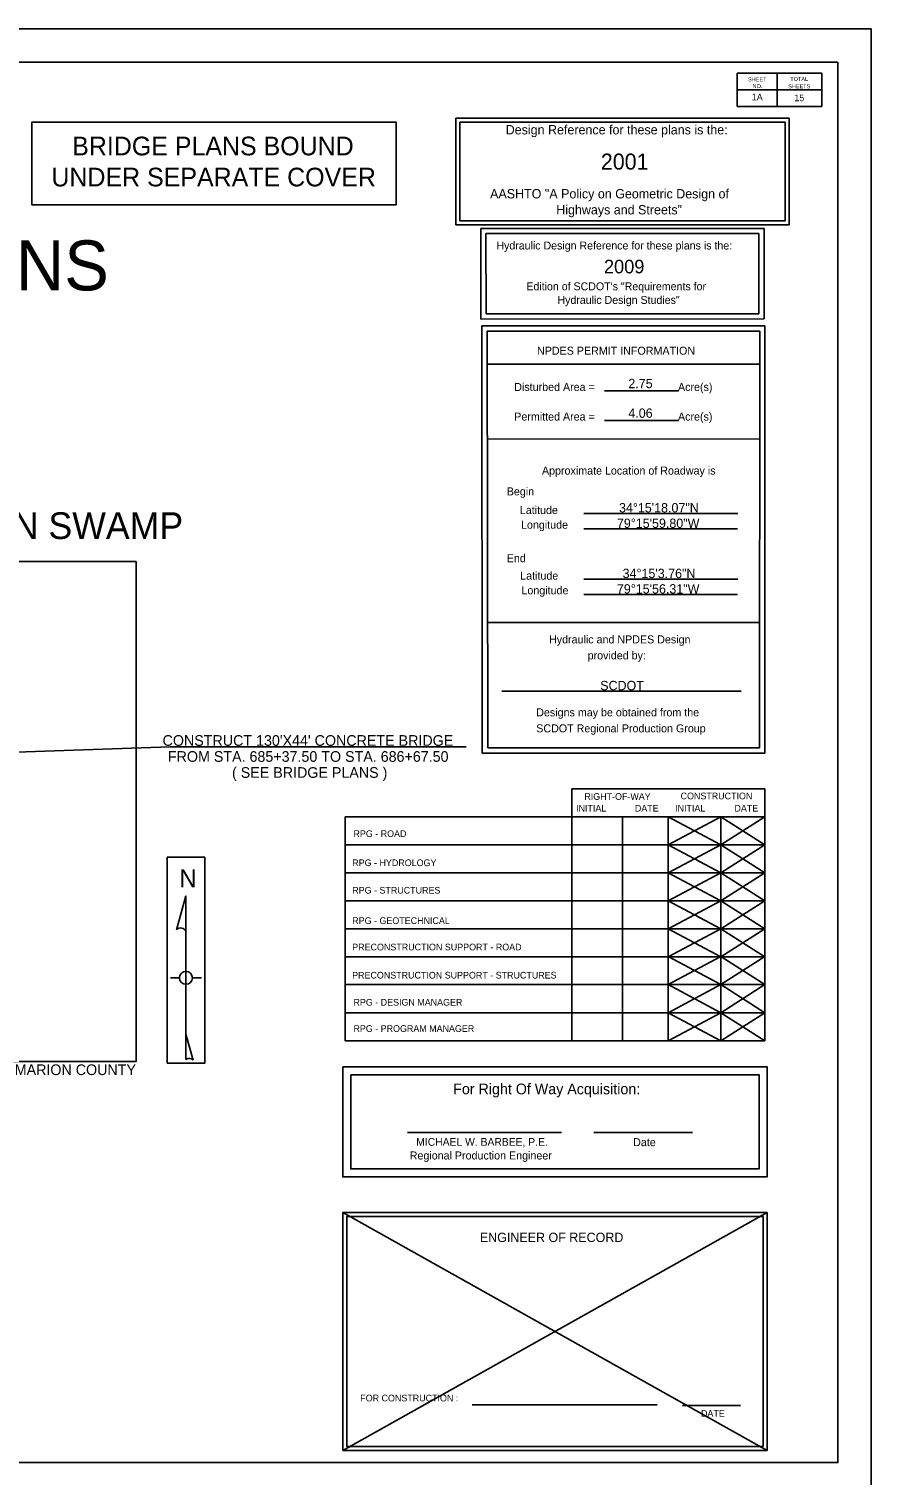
# Model space of a CAD drawing. Extents: x -13615 to 47191, y -1934 to 4415.
# Drawn here: x -11112 to -10480, y 3330 to 4415 of the extents above; entities that cross this region are included whole.
import ezdxf

# ---------------------------------------------------------------- set-up
doc = ezdxf.new("R2010")
doc.units = 0
for name, color, linetype in [('Default', 7, 'Continuous'), ('GN_TitleSheetMap', 7, 'Continuous'), ('RD_SHT_Bndy', 7, 'Continuous'), ('RD_SHT_IplotShp', 7, 'Continuous'), ('RD_SHT_Snap', 7, 'Continuous'), ('RD_SHT_TX', 7, 'Continuous'), ('RD_TX_TitleSht', 7, 'Continuous')]:
    doc.layers.add(name, color=color, linetype=linetype)

# ---------------------------------------------------------------- blocks, each defined once
blk = doc.blocks.new('GB2001')
at = {"layer": 'RD_SHT_Snap'}
for points in [[(-14.8, 12.6), (235.2, 12.6), (235.2, 92.6), (-14.8, 92.6)], [(-11.8, 15.6), (232.2, 15.6), (232.2, 89.6), (-11.8, 89.6)]]:
    blk.add_lwpolyline(points, close=True, dxfattribs=at)
for s, height, p in [('Design Reference for these plans is the:', 7, (22.6, 80.5)), ('2001', 12, (94, 54.1)), ('AASHTO "A Policy on Geometric Design of ', 7, (10.9, 32.5)), ('Highways and Streets"', 7, (60.5, 20.5))]:
    blk.add_text(s, height=height, dxfattribs=at).set_placement(p)

msp = doc.modelspace()

# ---------------------------------------------------------------- linework, layer by layer
at = {"layer": 'Default'}
for p, q in [((-11001.1, 3739.1), (-10994, 3764.4)), ((-10994, 3764.4), (-10994, 3737.8)), ((-10994, 3764.4), (-10994, 3641.7)), ((-11005.6, 3703), (-10998.8, 3703)), ((-10989.2, 3703), (-10982.3, 3703)), ((-10994, 3660.7), (-10994, 3641.7)), ((-10988.5, 3641.4), (-10994, 3660.7))]:
    msp.add_line(p, q, dxfattribs=at)
for points in [[(-11109.6, 4282.7), (-10836.2, 4282.7), (-10836.2, 4344.6), (-11109.6, 4344.6)], [(-11008, 3639), (-11008, 3793.4), (-10979.9, 3793.4), (-10979.9, 3639)]]:
    msp.add_lwpolyline(points, close=True, dxfattribs=at)
msp.add_circle((-10994, 3703), 4.83, dxfattribs=at)
for centre, radius, start, end in [((-10998, 3736.1), 4.3, 22.3707, 136.1387), ((-10991.4, 3638.7), 3.96, 43.3397, 130.5607)]:
    msp.add_arc(centre, radius, start, end, dxfattribs=at)
at = {"layer": 'GN_TitleSheetMap'}
msp.add_lwpolyline([(-11656.4, 3640.2), (-11031.4, 3640.2), (-11031.4, 4015.2), (-11656.4, 4015.2)], close=True, dxfattribs=at)
at = {"layer": 'RD_SHT_Bndy'}
for p, q in [((-12260.1, 4414.6), (-10500.2, 4414.6)), ((-10505.1, 4389.6), (-12180, 4389.6)), ((-10516.9, 4381.4), (-10580.4, 4381.4)), ((-10580.4, 4356.4), (-10580.4, 4381.4)), ((-10580.4, 4381.4), (-10550.4, 4381.4)), ((-10550.4, 4381.4), (-10550.4, 4356.4)), ((-10516.9, 4356.4), (-10516.9, 4381.4)), ((-10505, 3339.6), (-10505, 4389.6)), ((-10580, 4368.9), (-10517.2, 4368.9)), ((-10580.4, 4356.4), (-10516.9, 4356.4)), ((-10560.3, 4265), (-10772.8, 4265)), ((-10772.8, 4197), (-10772.8, 4265)), ((-10560.3, 4265), (-10560.3, 4197.1)), ((-10768.8, 4201), (-10768.9, 4261.1)), ((-10564.2, 4261.1), (-10768.9, 4261.1)), ((-10564.2, 4261.1), (-10564.3, 4201)), ((-10772.8, 4197), (-10560.3, 4197.1)), ((-10768.8, 4201), (-10564.3, 4201)), ((-10772, 4191.9), (-10559.6, 4191.9)), ((-10771.7, 3871.5), (-10772, 4191.9)), ((-10768.1, 4187.9), (-10563.5, 4188)), ((-10767.6, 3875.4), (-10768.1, 4187.9)), ((-10563.5, 4188), (-10563.7, 3875.4)), ((-10559.6, 4191.9), (-10559.7, 3871.5)), ((-10767.9, 4163.1), (-10563.6, 4163.1)), ((-10680.1, 4143.1), (-10624.6, 4143.1)), ((-10680.1, 4120.9), (-10624.6, 4120.9)), ((-10767.9, 4107), (-10563.7, 4107.2)), ((-10695.4, 4051.2), (-10579.9, 4051.2)), ((-10695.6, 4039.6), (-10580.1, 4039.6)), ((-10695.4, 4002), (-10579.9, 4002)), ((-10695.6, 3990.4), (-10580.1, 3990.4)), ((-10563.6, 3969.4), (-10767.7, 3969.4)), ((-10756.9, 3918), (-10577.4, 3918)), ((-10563.7, 3875.4), (-10767.6, 3875.4)), ((-10704.6, 3655.9), (-10704.6, 3844.8)), ((-10704.6, 3844.8), (-10559.7, 3844.8)), ((-10559.7, 3844.8), (-10559.7, 3655.9)), ((-10874.6, 3823.8), (-10559.7, 3823.8)), ((-10874.6, 3655.9), (-10874.6, 3823.8)), ((-10666.4, 3823.8), (-10666.4, 3655.9)), ((-10632.2, 3823.8), (-10632.2, 3655.9)), ((-10592.8, 3823.8), (-10592.8, 3655.9)), ((-10874.6, 3802.8), (-10559.7, 3802.8)), ((-10874.6, 3781.8), (-10559.7, 3781.8)), ((-10874.6, 3760.8), (-10559.7, 3760.8)), ((-10559.7, 3760.8), (-10559.7, 3739.8)), ((-10559.7, 3739.8), (-10874.6, 3739.8)), ((-10874.6, 3718.8), (-10559.7, 3718.8)), ((-10559.7, 3718.8), (-10559.7, 3697.9)), ((-10559.7, 3697.9), (-10874.6, 3697.9)), ((-10559.7, 3676.9), (-10874.6, 3676.9)), ((-10559.7, 3655.9), (-10874.6, 3655.9)), ((-10827.7, 3587.1), (-10712.2, 3587.1)), ((-10688.1, 3587.1), (-10613.9, 3587.1)), ((-10779.3, 3382.9), (-10640.6, 3382.9)), ((-10621.5, 3382.3), (-10578, 3382.3)), ((-12180.5, 3339.6), (-10504.7, 3339.6))]:
    msp.add_line(p, q, dxfattribs=at)
msp.add_lwpolyline([(-10771.7, 3871.5), (-10559.7, 3871.5)], dxfattribs=at)
for points in [[(-10876.3, 3636.4), (-10558, 3636.4), (-10558, 3553.7), (-10876.3, 3553.7)], [(-10870.3, 3630.4), (-10564, 3630.4), (-10564, 3559.7), (-10870.3, 3559.7)], [(-10876.3, 3348.6), (-10558, 3348.6), (-10558, 3527), (-10876.3, 3527)], [(-10873.3, 3351.6), (-10561, 3351.6), (-10561, 3524), (-10873.3, 3524)]]:
    msp.add_lwpolyline(points, close=True, dxfattribs=at)
at = {"layer": 'RD_SHT_IplotShp'}
msp.add_lwpolyline([(-12276, 4414.6), (-10480, 4414.6), (-10480, 3314.6), (-12276, 3314.6)], close=True, dxfattribs=at)
at = {"layer": 'RD_SHT_Snap'}
msp.add_line((-10480, 4414.6), (-10480, 3314.6), dxfattribs=at)
at = {"layer": 'RD_SHT_TX'}
for p in [(-11286.8, 3866.4), (-10783.7, 3876.2)]:
    msp.add_line(p, (-11005.7, 3876.2), dxfattribs=at)
at = {"layer": 'RD_TX_TitleSht'}
for p, q in [((-10592.8, 3823.8), (-10632.2, 3802.8)), ((-10592.8, 3823.8), (-10559.7, 3802.8)), ((-10592.8, 3802.8), (-10632.2, 3781.8)), ((-10592.8, 3802.8), (-10559.7, 3781.8)), ((-10592.8, 3781.8), (-10632.2, 3760.8)), ((-10592.8, 3781.8), (-10559.7, 3760.8)), ((-10592.8, 3760.8), (-10632.2, 3739.8)), ((-10592.8, 3760.8), (-10559.7, 3739.8)), ((-10592.8, 3739.8), (-10632.2, 3718.8)), ((-10592.8, 3739.8), (-10559.7, 3718.8)), ((-10592.8, 3718.9), (-10632.2, 3697.9)), ((-10592.8, 3718.9), (-10559.7, 3697.9)), ((-10592.8, 3697.9), (-10632.2, 3676.9)), ((-10592.8, 3697.9), (-10559.7, 3676.9)), ((-10592.8, 3676.9), (-10632.2, 3655.9)), ((-10592.8, 3676.9), (-10559.7, 3655.9)), ((-10558, 3527), (-10876.3, 3348.6)), ((-10876.3, 3527), (-10558, 3348.6))]:
    msp.add_line(p, q, dxfattribs=at)
for points in [[(-10632.2, 3823.8), (-10592.8, 3802.8), (-10559.7, 3823.8)], [(-10632.2, 3802.8), (-10592.8, 3781.8), (-10559.7, 3802.8)], [(-10632.2, 3781.8), (-10592.8, 3760.8), (-10559.7, 3781.8)], [(-10632.2, 3760.8), (-10592.8, 3739.8), (-10559.7, 3760.8)], [(-10632.2, 3739.8), (-10592.8, 3718.8), (-10559.7, 3739.8)], [(-10632.2, 3718.9), (-10592.8, 3697.9), (-10559.7, 3718.9)], [(-10632.2, 3697.9), (-10592.8, 3676.9), (-10559.7, 3697.9)], [(-10632.2, 3676.9), (-10592.8, 3655.9), (-10559.7, 3676.9)]]:
    msp.add_lwpolyline(points, dxfattribs=at)

# ---------------------------------------------------------------- block references
at = {"layer": 'RD_SHT_Bndy'}
msp.add_blockref('GB2001', (-10776.7, 4255), dxfattribs=at)

# ---------------------------------------------------------------- texts
at = {"layer": 'Default'}
for s, height, p in [('   BRIDGE PLANS BOUND', 14, (-11094.9, 4319.8)), ('UNDER SEPARATE COVER', 14, (-11094.9, 4296.5)), ('Hydraulic Design Reference for these plans is the:', 5.949, (-10761.1, 4249.2)), ('2009', 10.2, (-10680.4, 4231.3)), ('Edition of SCDOT\'s "Requirements for ', 5.949, (-10738.6, 4218.6)), ('Hydraulic Design Studies"', 5.949, (-10715.3, 4208.4))]:
    msp.add_text(s, height=height, dxfattribs=at).set_placement(p)
msp.add_text('N', height=13.4, rotation=360, dxfattribs=at).set_placement((-10998.9, 3771))
at = {"layer": 'RD_SHT_TX'}
for s, height, p in [('SHEET', 3, (-10572.3, 4375.3)), ('NO.', 3, (-10568.9, 4370.2)), ('SHEETS', 3, (-10542.2, 4370.1)), ('TOTAL', 3, (-10540.6, 4375.6)), ('1A', 5, (-10569.5, 4361.1)), ('15', 5, (-10537.6, 4360.4)), ('PROPOSED PLANS', 37.5, (-11514.4, 4218.5)), ('NPDES PERMIT INFORMATION', 6, (-10730.6, 4170.3)), ('Disturbed Area =                            Acre(s)', 6, (-10747.7, 4143.1)), ('Permitted Area =                            Acre(s)', 6, (-10747.7, 4120.9)), ('Approximate Location of Roadway is', 6, (-10726.9, 4080.4)), ('Begin', 6, (-10753.3, 4064.8)), ('Latitude', 6, (-10743.5, 4050.8)), ('BRIDGE REPLACEMENT OVER MAIDEN DOWN SWAMP', 20, (-11701.9, 4032.1)), ('Longitude', 6, (-10742.6, 4039.8)), ('End', 6, (-10753.3, 4014.7)), ('Latitude', 6, (-10743.2, 4001.6)), ('Longitude', 6, (-10742.3, 3990.6)), ('Hydraulic and NPDES Design', 6, (-10721.6, 3953.8)), ('             provided by:', 6, (-10721.6, 3941.8)), ('Designs may be obtained from the ', 6, (-10731.2, 3899.1)), ('SCDOT Regional Production Group', 6, (-10731.2, 3887.1)), ('RPG - ROAD', 5, (-10868.3, 3808.6)), ('RPG - HYDROLOGY ', 4.998, (-10869.2, 3786.8)), ('RPG - STRUCTURES', 4.998, (-10869.2, 3766.2)), ('RPG - GEOTECHNICAL', 4.998, (-10869.2, 3743.4)), ('PRECONSTRUCTION SUPPORT - ROAD', 4.998, (-10869.2, 3723.6)), ('PRECONSTRUCTION SUPPORT - STRUCTURES', 4.998, (-10869.3, 3702.5)), ('RPG - DESIGN MANAGER', 4.998, (-10868.3, 3682.2)), ('RPG - PROGRAM MANAGER', 4.998, (-10868.3, 3662.5)), ('MARION COUNTY ', 8, (-11122.4, 3630.1)), ('For Right Of Way Acquisition:', 8, (-10793.5, 3615.7)), ('Date', 6, (-10658.5, 3576.8)), ('Regional Production Engineer', 6, (-10826.1, 3566.8)), ('ENGINEER OF RECORD', 7, (-10773.5, 3504.9)), ('FOR CONSTRUCTION :', 5, (-10863.2, 3385.4)), ('DATE', 5, (-10607.6, 3373.9))]:
    msp.add_text(s, height=height, dxfattribs=at).set_placement(p)
for s, height, p in [('RIGHT-OF-WAY', 4.998, (-10695.1, 3836.5)), ('CONSTRUCTION', 4.998, (-10622.9, 3836.9)), ('INITIAL', 5, (-10701.3, 3827.7)), ('DATE', 5, (-10657.2, 3827.7)), ('INITIAL', 5, (-10627, 3827.7)), ('DATE', 5, (-10582.5, 3827.7))]:
    msp.add_text(s, height=height, rotation=360, dxfattribs=at).set_placement(p)
at = {"layer": 'RD_TX_TitleSht'}
for s, height, p in [(' 2.75', 7, (-10664.7, 4145.2)), (' 4.06', 7, (-10664.7, 4123)), (' 34°15\'18.07"N', 7, (-10671.7, 4052)), (' 79°15\'59.80"W', 7, (-10673.3, 4040.4)), (' 34°15\'3.76"N', 7, (-10669, 4002.8)), (' 79°15\'56.31"W', 7, (-10673.3, 3991.2)), ('SCDOT', 7, (-10683.2, 3918.7)), ("CONSTRUCT 130'X44' CONCRETE BRIDGE", 8, (-11011.5, 3877)), ('FROM STA. 685+37.50 TO STA. 686+67.50', 8, (-11007.5, 3865)), ('( SEE BRIDGE PLANS )', 8, (-10959.4, 3853)), ('MICHAEL W. BARBEE, P.E.', 5.8, (-10821.2, 3577.1))]:
    msp.add_text(s, height=height, dxfattribs=at).set_placement(p)

doc.saveas('drawing.dxf')
